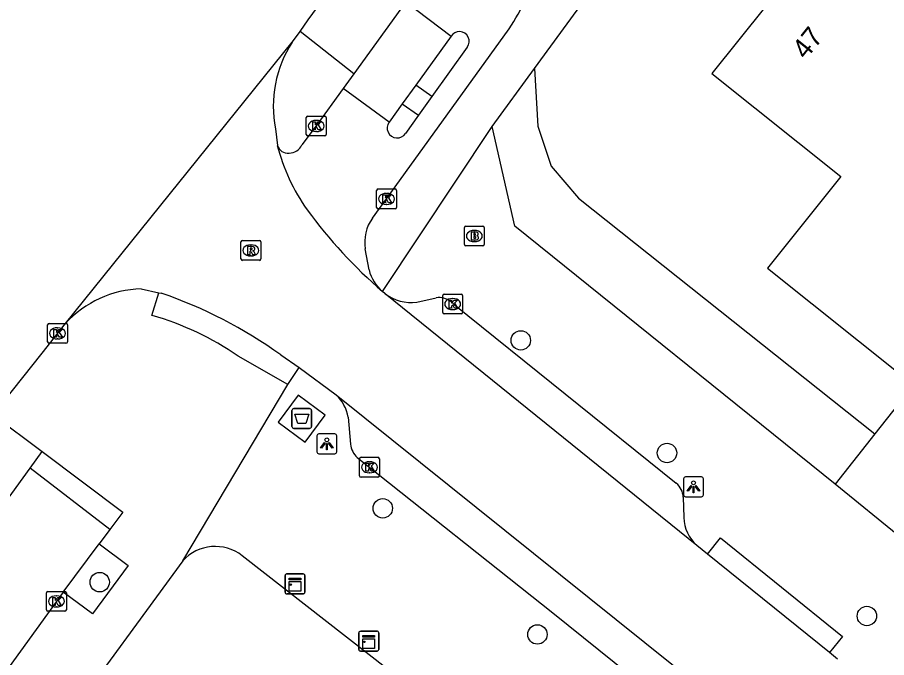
# Model space of a CAD drawing. Extents: x 160107 to 160928, y 382056 to 382918.
# Drawn here: x 160421.79 to 160465.57, y 382582.18 to 382614.43 of the extents above; entities that cross this region are included whole.
import ezdxf

# ---------------------------------------------------------------- set-up
doc = ezdxf.new("R2010")
doc.units = 0
for name, color, linetype in [('IMGEO_Afval_apart_plaats', 7, 'Continuous'), ('IMGEO_Boom', 7, 'Continuous'), ('IMGEO_Brandkraan', 7, 'Continuous'), ('IMGEO_Groenvoorziening', 7, 'Continuous'), ('IMGEO_Kast', 7, 'Continuous'), ('IMGEO_Kolk', 7, 'Continuous'), ('IMGEO_Lichtpunt', 7, 'Continuous'), ('IMGEO_Pand', 7, 'Continuous'), ('IMGEO_Pand_nummerreeks', 7, 'Continuous'), ('IMGEO_Rijbaan_lokaal_gesloten', 7, 'Continuous'), ('IMGEO_Rijbaan_lokaal_open', 7, 'Continuous'), ('IMGEO_Rioolput', 7, 'Continuous'), ('IMGEO_Voetpad_gesloten', 7, 'Continuous'), ('IMGEO_Voetpad_open', 7, 'Continuous')]:
    doc.layers.add(name, color=color, linetype=linetype)

msp = doc.modelspace()

# ---------------------------------------------------------------- linework, layer by layer
at = {"layer": 'IMGEO_Afval_apart_plaats'}
for p, q in [((160435.613, 382593.824), (160435.613, 382594.624)), ((160435.613, 382594.624), (160435.613, 382593.824)), ((160435.713, 382594.724), (160436.503, 382594.724)), ((160436.503, 382594.724), (160435.713, 382594.724)), ((160436.603, 382594.624), (160436.603, 382593.824)), ((160436.603, 382593.824), (160436.603, 382594.624)), ((160436.503, 382593.724), (160435.713, 382593.724)), ((160435.713, 382593.724), (160436.503, 382593.724))]:
    msp.add_line(p, q, dxfattribs=at)
msp.add_lwpolyline([(160435.756, 382594.438), (160436.46, 382594.438), (160436.311, 382593.968), (160435.905, 382593.968), (160435.756, 382594.438)], dxfattribs=at)
for centre, start, end in [((160435.713, 382594.624), 90, 180), ((160435.713, 382594.624), 90, 180), ((160436.503, 382594.624), 0, 90), ((160436.503, 382594.624), 360, 90), ((160435.713, 382593.824), 180, 270), ((160435.713, 382593.824), 180, 270), ((160436.503, 382593.824), 270, 0), ((160436.503, 382593.824), 270, 0)]:
    msp.add_arc(centre, 0.1, start, end, dxfattribs=at)
at = {"layer": 'IMGEO_Boom'}
for centre in [(160447.142, 382598.162), (160454.506, 382592.489), (160440.191, 382589.702), (160425.936, 382585.981), (160464.571, 382584.275), (160447.979, 382583.347)]:
    msp.add_circle(centre, 0.489, dxfattribs=at)
at = {"layer": 'IMGEO_Brandkraan'}
for p, q in [((160444.302, 382602.995), (160444.302, 382603.847)), ((160444.377, 382603.921), (160445.229, 382603.921)), ((160444.79, 382603.701), (160444.815, 382603.701)), ((160445.303, 382603.847), (160445.303, 382602.995)), ((160445.229, 382602.921), (160444.377, 382602.921)), ((160444.813, 382603.141), (160444.788, 382603.141))]:
    msp.add_line(p, q, dxfattribs=at)
for points in [[(160444.302, 382602.995), (160444.302, 382603.847)], [(160444.377, 382603.921), (160445.229, 382603.921)], [(160444.65, 382603.621), (160444.65, 382603.221), (160444.863, 382603.221)], [(160444.881, 382603.621), (160444.65, 382603.621)], [(160445.303, 382603.847), (160445.303, 382602.995)], [(160444.829, 382603.54), (160444.775, 382603.54), (160444.775, 382603.464)], [(160444.775, 382603.464), (160444.828, 382603.464)], [(160444.837, 382603.388), (160444.775, 382603.388), (160444.775, 382603.307)], [(160444.775, 382603.307), (160444.837, 382603.307)], [(160445.229, 382602.921), (160444.377, 382602.921)]]:
    msp.add_lwpolyline(points, dxfattribs=at)
for centre, radius, start, end in [((160444.379, 382603.845), 0.0765, 91.552, 178.448), ((160444.379, 382603.845), 0.0765, 91.552, 178.448), ((160444.885, 382603.476), 0.145, 59.4692, 91.5367), ((160444.91, 382603.523), 0.0922, 285.5137, 58.1501), ((160445.227, 382603.845), 0.0765, 1.552, 88.448), ((160445.227, 382603.845), 0.0765, 1.552, 88.448), ((160444.83, 382603.502), 0.0379, 267.8285, 90.9355), ((160444.838, 382603.347), 0.0404, 269.8759, 90.5077), ((160444.869, 382603.472), 0.251, 268.6676, 293.5347), ((160444.915, 382603.331), 0.105, 301.3115, 78.989), ((160444.379, 382602.997), 0.0765, 181.552, 268.448), ((160444.379, 382602.997), 0.0765, 181.552, 268.448), ((160445.227, 382602.997), 0.0765, 271.552, 358.448), ((160445.227, 382602.997), 0.0765, 271.552, 358.448)]:
    msp.add_arc(centre, radius, start, end, dxfattribs=at)
for centre, major_axis, ratio, start_param, end_param in [((160444.789, 382603.421), (-0.387, 0.002), 0.722429, 4.712389, 7.853982), ((160444.814, 382603.421), (-0.39, 0.002), 0.717154, 1.570796, 4.712389)]:
    msp.add_ellipse(centre, major_axis=major_axis, ratio=ratio, start_param=start_param, end_param=end_param, dxfattribs=at)
at = {"layer": 'IMGEO_Groenvoorziening'}
msp.add_lwpolyline([(160447.829, 382611.851), (160448.003, 382608.946), (160448.669, 382606.931), (160450.051, 382605.319), (160464.977, 382593.454)], dxfattribs=at)
at = {"layer": 'IMGEO_Kast'}
for p, q in [((160435.274, 382585.47), (160435.274, 382586.311)), ((160435.274, 382586.311), (160435.274, 382585.47)), ((160435.349, 382586.395), (160436.19, 382586.395)), ((160436.19, 382586.395), (160435.349, 382586.395)), ((160436.274, 382586.32), (160436.274, 382585.479)), ((160436.274, 382585.479), (160436.274, 382586.32)), ((160436.199, 382585.395), (160435.358, 382585.395)), ((160435.358, 382585.395), (160436.199, 382585.395)), ((160439.061, 382583.509), (160439.902, 382583.509)), ((160439.902, 382583.509), (160439.061, 382583.509)), ((160438.986, 382582.584), (160438.986, 382583.425)), ((160438.986, 382583.425), (160438.986, 382582.584)), ((160439.986, 382583.434), (160439.986, 382582.593)), ((160439.986, 382582.593), (160439.986, 382583.434)), ((160439.911, 382582.509), (160439.07, 382582.509)), ((160439.07, 382582.509), (160439.911, 382582.509))]:
    msp.add_line(p, q, dxfattribs=at)
for points in [[(160435.469, 382586.185), (160436.069, 382586.185), (160436.069, 382586.1), (160435.469, 382586.1), (160435.469, 382586.185)], [(160435.469, 382586.01), (160436.069, 382586.01), (160436.069, 382585.521), (160435.469, 382585.521), (160435.469, 382586.01)], [(160439.181, 382583.299), (160439.781, 382583.299), (160439.781, 382583.214), (160439.181, 382583.214), (160439.181, 382583.299)], [(160439.181, 382583.124), (160439.781, 382583.124), (160439.781, 382582.635), (160439.181, 382582.635), (160439.181, 382583.124)]]:
    msp.add_lwpolyline(points, dxfattribs=at)
for centre in [(160435.553, 382585.859), (160439.265, 382582.973)]:
    msp.add_circle(centre, 0.0377, dxfattribs=at)
for centre, start, end in [((160435.352, 382586.317), 92.4484, 184.2845), ((160435.352, 382586.317), 92.4484, 184.2845), ((160436.196, 382586.317), 2.4484, 94.2845), ((160436.196, 382586.317), 2.4484, 94.2845), ((160435.352, 382585.473), 182.4484, 274.2845), ((160435.352, 382585.473), 182.4484, 274.2845), ((160436.196, 382585.473), 272.4484, 4.2845), ((160436.196, 382585.473), 272.4484, 4.2845), ((160439.064, 382583.431), 92.4484, 184.2845), ((160439.064, 382583.431), 92.4484, 184.2845), ((160439.908, 382583.431), 2.4484, 94.2845), ((160439.908, 382583.431), 2.4484, 94.2845), ((160439.064, 382582.587), 182.4484, 274.2845), ((160439.064, 382582.587), 182.4484, 274.2845), ((160439.908, 382582.587), 272.4484, 4.2845), ((160439.908, 382582.587), 272.4484, 4.2845)]:
    msp.add_arc(centre, 0.0779, start, end, dxfattribs=at)
at = {"layer": 'IMGEO_Kolk'}
for p, q in [((160436.34, 382608.538), (160436.34, 382609.39)), ((160436.415, 382609.464), (160437.267, 382609.464)), ((160437.341, 382609.39), (160437.341, 382608.538)), ((160436.828, 382609.244), (160436.853, 382609.244)), ((160437.267, 382608.464), (160436.415, 382608.464)), ((160436.851, 382608.684), (160436.826, 382608.684)), ((160439.955, 382605.789), (160440.807, 382605.789)), ((160439.88, 382604.863), (160439.88, 382605.715)), ((160440.368, 382605.569), (160440.393, 382605.569)), ((160440.881, 382605.715), (160440.881, 382604.863)), ((160440.391, 382605.009), (160440.366, 382605.009)), ((160440.807, 382604.789), (160439.955, 382604.789)), ((160443.21, 382599.566), (160443.21, 382600.418)), ((160443.285, 382600.492), (160444.137, 382600.492)), ((160443.698, 382600.272), (160443.723, 382600.272)), ((160444.211, 382600.418), (160444.211, 382599.566)), ((160443.721, 382599.712), (160443.696, 382599.712)), ((160444.137, 382599.492), (160443.285, 382599.492)), ((160423.31, 382598.09), (160423.31, 382598.942)), ((160423.385, 382599.016), (160424.237, 382599.016)), ((160423.798, 382598.796), (160423.823, 382598.796)), ((160424.311, 382598.942), (160424.311, 382598.09)), ((160424.237, 382598.016), (160423.385, 382598.016)), ((160423.821, 382598.236), (160423.796, 382598.236)), ((160439.095, 382592.271), (160439.947, 382592.271)), ((160439.02, 382591.345), (160439.02, 382592.197)), ((160439.508, 382592.051), (160439.533, 382592.051)), ((160440.021, 382592.197), (160440.021, 382591.345)), ((160439.531, 382591.491), (160439.506, 382591.491)), ((160439.947, 382591.271), (160439.095, 382591.271)), ((160423.254, 382584.587), (160423.254, 382585.439)), ((160423.329, 382585.513), (160424.181, 382585.513)), ((160423.742, 382585.293), (160423.767, 382585.293)), ((160424.255, 382585.439), (160424.255, 382584.587)), ((160424.181, 382584.513), (160423.329, 382584.513)), ((160423.765, 382584.733), (160423.74, 382584.733))]:
    msp.add_line(p, q, dxfattribs=at)
for points in [[(160436.34, 382608.538), (160436.34, 382609.39)], [(160436.415, 382609.464), (160437.267, 382609.464)], [(160437.341, 382609.39), (160437.341, 382608.538)], [(160436.661, 382609.164), (160436.784, 382609.164), (160436.784, 382609.013), (160436.914, 382609.164), (160437.078, 382609.164), (160436.932, 382609.013), (160437.085, 382608.764), (160436.933, 382608.764), (160436.848, 382608.928), (160436.784, 382608.861), (160436.784, 382608.764), (160436.661, 382608.764), (160436.661, 382609.164)], [(160437.267, 382608.464), (160436.415, 382608.464)], [(160439.955, 382605.789), (160440.807, 382605.789)], [(160439.88, 382604.863), (160439.88, 382605.715)], [(160440.201, 382605.489), (160440.324, 382605.489), (160440.324, 382605.338), (160440.454, 382605.489), (160440.618, 382605.489), (160440.472, 382605.338), (160440.625, 382605.089), (160440.473, 382605.089), (160440.388, 382605.253), (160440.324, 382605.186), (160440.324, 382605.089), (160440.201, 382605.089), (160440.201, 382605.489)], [(160440.881, 382605.715), (160440.881, 382604.863)], [(160440.807, 382604.789), (160439.955, 382604.789)], [(160443.21, 382599.566), (160443.21, 382600.418)], [(160443.285, 382600.492), (160444.137, 382600.492)], [(160443.531, 382600.192), (160443.654, 382600.192), (160443.654, 382600.041), (160443.784, 382600.192), (160443.948, 382600.192), (160443.802, 382600.041), (160443.955, 382599.792), (160443.803, 382599.792), (160443.718, 382599.956), (160443.654, 382599.889), (160443.654, 382599.792), (160443.531, 382599.792), (160443.531, 382600.192)], [(160444.211, 382600.418), (160444.211, 382599.566)], [(160444.137, 382599.492), (160443.285, 382599.492)], [(160423.31, 382598.09), (160423.31, 382598.942)], [(160423.385, 382599.016), (160424.237, 382599.016)], [(160424.311, 382598.942), (160424.311, 382598.09)], [(160423.631, 382598.716), (160423.754, 382598.716), (160423.754, 382598.565), (160423.884, 382598.716), (160424.048, 382598.716), (160423.902, 382598.565), (160424.055, 382598.316), (160423.903, 382598.316), (160423.818, 382598.48), (160423.754, 382598.413), (160423.754, 382598.316), (160423.631, 382598.316), (160423.631, 382598.716)], [(160424.237, 382598.016), (160423.385, 382598.016)], [(160439.095, 382592.271), (160439.947, 382592.271)], [(160439.02, 382591.345), (160439.02, 382592.197)], [(160439.341, 382591.971), (160439.464, 382591.971), (160439.464, 382591.82), (160439.594, 382591.971), (160439.758, 382591.971), (160439.612, 382591.82), (160439.765, 382591.571), (160439.613, 382591.571), (160439.528, 382591.735), (160439.464, 382591.668), (160439.464, 382591.571), (160439.341, 382591.571), (160439.341, 382591.971)], [(160440.021, 382592.197), (160440.021, 382591.345)], [(160439.947, 382591.271), (160439.095, 382591.271)], [(160423.254, 382584.587), (160423.254, 382585.439)], [(160423.329, 382585.513), (160424.181, 382585.513)], [(160423.575, 382585.213), (160423.698, 382585.213), (160423.698, 382585.062), (160423.828, 382585.213), (160423.992, 382585.213), (160423.846, 382585.062), (160423.999, 382584.813), (160423.847, 382584.813), (160423.762, 382584.977), (160423.698, 382584.91), (160423.698, 382584.813), (160423.575, 382584.813), (160423.575, 382585.213)], [(160424.255, 382585.439), (160424.255, 382584.587)], [(160424.181, 382584.513), (160423.329, 382584.513)]]:
    msp.add_lwpolyline(points, dxfattribs=at)
for centre, start, end in [((160436.417, 382609.388), 91.552, 178.448), ((160436.417, 382609.388), 91.552, 178.448), ((160437.265, 382609.388), 1.552, 88.448), ((160437.265, 382609.388), 1.552, 88.448), ((160436.417, 382608.54), 181.552, 268.448), ((160436.417, 382608.54), 181.552, 268.448), ((160437.265, 382608.54), 271.552, 358.448), ((160437.265, 382608.54), 271.552, 358.448), ((160439.957, 382605.713), 91.552, 178.448), ((160439.957, 382605.713), 91.552, 178.448), ((160440.805, 382605.713), 1.552, 88.448), ((160440.805, 382605.713), 1.552, 88.448), ((160439.957, 382604.865), 181.552, 268.448), ((160439.957, 382604.865), 181.552, 268.448), ((160440.805, 382604.865), 271.552, 358.448), ((160440.805, 382604.865), 271.552, 358.448), ((160443.287, 382600.416), 91.552, 178.448), ((160443.287, 382600.416), 91.552, 178.448), ((160444.135, 382600.416), 1.552, 88.448), ((160444.135, 382600.416), 1.552, 88.448), ((160443.287, 382599.568), 181.552, 268.448), ((160443.287, 382599.568), 181.552, 268.448), ((160444.135, 382599.568), 271.552, 358.448), ((160444.135, 382599.568), 271.552, 358.448), ((160423.387, 382598.94), 91.552, 178.448), ((160423.387, 382598.94), 91.552, 178.448), ((160424.235, 382598.94), 1.552, 88.448), ((160424.235, 382598.94), 1.552, 88.448), ((160423.387, 382598.092), 181.552, 268.448), ((160423.387, 382598.092), 181.552, 268.448), ((160424.235, 382598.092), 271.552, 358.448), ((160424.235, 382598.092), 271.552, 358.448), ((160439.097, 382592.195), 91.552, 178.448), ((160439.097, 382592.195), 91.552, 178.448), ((160439.945, 382592.195), 1.552, 88.448), ((160439.945, 382592.195), 1.552, 88.448), ((160439.097, 382591.347), 181.552, 268.448), ((160439.097, 382591.347), 181.552, 268.448), ((160439.945, 382591.347), 271.552, 358.448), ((160439.945, 382591.347), 271.552, 358.448), ((160423.331, 382585.437), 91.552, 178.448), ((160423.331, 382585.437), 91.552, 178.448), ((160424.179, 382585.437), 1.552, 88.448), ((160424.179, 382585.437), 1.552, 88.448), ((160423.331, 382584.589), 181.552, 268.448), ((160423.331, 382584.589), 181.552, 268.448), ((160424.179, 382584.589), 271.552, 358.448), ((160424.179, 382584.589), 271.552, 358.448)]:
    msp.add_arc(centre, 0.0765, start, end, dxfattribs=at)
for centre, major_axis, ratio, start_param, end_param in [((160436.827, 382608.964), (-0.387, 0.002), 0.722429, 4.712389, 7.853982), ((160436.852, 382608.964), (-0.39, 0.002), 0.717154, 1.570796, 4.712389), ((160440.367, 382605.289), (-0.387, 0.002), 0.722429, 4.712389, 7.853982), ((160440.392, 382605.289), (-0.39, 0.002), 0.717154, 1.570796, 4.712389), ((160443.697, 382599.992), (-0.387, 0.002), 0.722429, 4.712389, 7.853982), ((160443.722, 382599.992), (-0.39, 0.002), 0.717154, 1.570796, 4.712389), ((160423.797, 382598.516), (-0.387, 0.002), 0.722429, 4.712389, 7.853982), ((160423.822, 382598.516), (-0.39, 0.002), 0.717154, 1.570796, 4.712389), ((160439.507, 382591.771), (-0.387, 0.002), 0.722429, 4.712389, 7.853982), ((160439.532, 382591.771), (-0.39, 0.002), 0.717154, 1.570796, 4.712389), ((160423.741, 382585.013), (-0.387, 0.002), 0.722429, 4.712389, 7.853982), ((160423.766, 382585.013), (-0.39, 0.002), 0.717154, 1.570796, 4.712389)]:
    msp.add_ellipse(centre, major_axis=major_axis, ratio=ratio, start_param=start_param, end_param=end_param, dxfattribs=at)
at = {"layer": 'IMGEO_Lichtpunt'}
for p, q in [((160436.875, 382593.352), (160436.875, 382592.545)), ((160436.875, 382593.352), (160436.875, 382592.545)), ((160437.777, 382593.447), (160436.969, 382593.447)), ((160437.777, 382593.447), (160436.969, 382593.447)), ((160437.871, 382592.545), (160437.871, 382593.352)), ((160437.871, 382592.545), (160437.871, 382593.352)), ((160436.969, 382592.451), (160437.777, 382592.451)), ((160436.969, 382592.451), (160437.777, 382592.451)), ((160455.34, 382591.188), (160455.34, 382590.381)), ((160455.34, 382591.188), (160455.34, 382590.381)), ((160456.242, 382591.283), (160455.434, 382591.283)), ((160456.242, 382591.283), (160455.434, 382591.283)), ((160456.336, 382590.381), (160456.336, 382591.188)), ((160456.336, 382590.381), (160456.336, 382591.188)), ((160455.434, 382590.287), (160456.242, 382590.287)), ((160455.434, 382590.287), (160456.242, 382590.287))]:
    msp.add_line(p, q, dxfattribs=at)
for points in [[(160437.249, 382593.016), (160437.288, 382592.988), (160437.1, 382592.726), (160437.062, 382592.753), (160437.249, 382593.016)], [(160437.351, 382592.968), (160437.398, 382592.968), (160437.398, 382592.646), (160437.351, 382592.646), (160437.351, 382592.968)], [(160437.461, 382592.988), (160437.499, 382593.015), (160437.686, 382592.753), (160437.647, 382592.725), (160437.461, 382592.988)], [(160455.714, 382590.852), (160455.753, 382590.824), (160455.565, 382590.562), (160455.527, 382590.589), (160455.714, 382590.852)], [(160455.816, 382590.804), (160455.863, 382590.804), (160455.863, 382590.482), (160455.816, 382590.482), (160455.816, 382590.804)], [(160455.926, 382590.824), (160455.964, 382590.851), (160456.151, 382590.589), (160456.112, 382590.561), (160455.926, 382590.824)]]:
    msp.add_lwpolyline(points, dxfattribs=at)
for centre in [(160437.374, 382593.15), (160455.839, 382590.986)]:
    msp.add_circle(centre, 0.0994, dxfattribs=at)
for centre, start, end in [((160436.969, 382593.352), 90, 180), ((160436.969, 382593.352), 90, 180), ((160437.777, 382593.352), 0, 90), ((160437.777, 382593.352), 0, 90), ((160436.969, 382592.545), 180, 270), ((160436.969, 382592.545), 180, 270), ((160437.777, 382592.545), 270, 0), ((160437.777, 382592.545), 270, 360), ((160455.434, 382591.188), 90, 180), ((160455.434, 382591.188), 90, 180), ((160456.242, 382591.188), 0, 90), ((160456.242, 382591.188), 0, 90), ((160455.434, 382590.381), 180, 270), ((160455.434, 382590.381), 180, 270), ((160456.242, 382590.381), 270, 0), ((160456.242, 382590.381), 270, 360)]:
    msp.add_arc(centre, 0.0946, start, end, dxfattribs=at)
at = {"layer": 'IMGEO_Pand'}
msp.add_lwpolyline([(160475.509, 382618.245), (160472.259, 382622.139), (160472.107, 382621.949), (160466.446, 382614.871), (160462.136, 382618.318), (160456.77, 382611.608), (160463.264, 382606.415), (160459.571, 382601.796), (160466.396, 382596.337), (160471.313, 382602.486), (160467.185, 382606.098), (160474.119, 382614.769), (160475.347, 382614.015), (160477.432, 382615.94)], dxfattribs=at)
at = {"layer": 'IMGEO_Rijbaan_lokaal_gesloten'}
for points in [[(160436.025, 382613.729), (160436.428, 382614.314), (160437.427, 382615.674), (160438.434, 382616.761)], [(160435.632, 382613.186), (160435.89, 382613.533), (160436.025, 382613.729)], [(160424.212, 382599.014), (160435.632, 382613.186)], [(160420.558, 382594.413), (160423.042, 382597.522), (160424.212, 382599.014)]]:
    msp.add_lwpolyline(points, dxfattribs=at)
at = {"layer": 'IMGEO_Rijbaan_lokaal_open'}
for points in [[(160525.477, 382626.898), (160516.443, 382636.034), (160510.687, 382632.435), (160500, 382625.753), (160480.01, 382613.255), (160480.277, 382612.822), (160464.977, 382593.454)], [(160441.354, 382615.212), (160443.631, 382613.481)], [(160441.104, 382614.866), (160438.732, 382611.585)], [(160439.667, 382604.311), (160440.376, 382605.29), (160446.562, 382613.866)], [(160443.631, 382613.481), (160441.854, 382611.023)], [(160444.442, 382612.935), (160442.662, 382610.445)], [(160438.732, 382611.585), (160438.202, 382610.852)], [(160438.202, 382610.852), (160436.838, 382608.964), (160436.118, 382608.006)], [(160440.505, 382609.157), (160438.202, 382610.852)], [(160441.854, 382611.023), (160441.175, 382610.083)], [(160442.662, 382610.445), (160441.988, 382609.502)], [(160441.175, 382610.083), (160440.505, 382609.157)], [(160441.988, 382609.502), (160441.333, 382608.586)], [(160434.791, 382608.815), (160434.881, 382607.985)], [(160439.498, 382601.708), (160439.308, 382602.777)], [(160428.021, 382600.754), (160428.919, 382600.565)], [(160428.919, 382600.565), (160429.026, 382600.543)], [(160440.316, 382600.508), (160440.177, 382600.621)], [(160456.007, 382587.831), (160440.316, 382600.508)], [(160435.049, 382597.428), (160435.985, 382596.798)], [(160435.985, 382596.798), (160437.847, 382595.414)], [(160437.847, 382595.414), (160450.577, 382585.198), (160483.799, 382558.523)], [(160464.977, 382593.454), (160462.972, 382590.915)], [(160422.43, 382591.723), (160423.04, 382592.568)], [(160423.04, 382592.568), (160427.101, 382589.515), (160426.45, 382588.641)], [(160415.332, 382581.933), (160422.43, 382591.723)], [(160426.45, 382588.641), (160422.43, 382591.723)], [(160466.307, 382588.202), (160462.972, 382590.915)], [(160426.45, 382588.641), (160425.903, 382587.906)], [(160424.094, 382585.479), (160425.903, 382587.906)], [(160456.544, 382587.398), (160456.007, 382587.831)], [(160462.683, 382582.44), (160456.544, 382587.398)], [(160424.094, 382585.479), (160418.415, 382577.656)], [(160463.099, 382582.104), (160462.683, 382582.44)]]:
    msp.add_lwpolyline(points, dxfattribs=at)
for centre, radius, start, end in [((160436.728, 382620.328), 11.768, 326.6897, 343.1987), ((160444.052, 382613.231), 0.49, 322.8436, 149.2561), ((160440.571, 382609.969), 5.894, 146.9227, 191.2956), ((160440.913, 382608.863), 0.503, 144.2679, 326.5508), ((160435.41, 382608.149), 0.554, 197.2102, 276.8437), ((160444.244, 382610.353), 9.658, 194.192, 215.5262), ((160435.469, 382608.32), 0.721, 270.5539, 334.1919), ((160456.62, 382619.565), 25.084, 216.2246, 229.0426), ((160441.327, 382603.114), 2.047, 144.1915, 189.4649), ((160441.63, 382602.284), 2.208, 195.1211, 228.8612), ((160428.151, 382595.43), 5.325, 91.3982, 137.7049), ((160421.506, 382578.622), 23.175, 54.2404, 71.0651)]:
    msp.add_arc(centre, radius, start, end, dxfattribs=at)
at = {"layer": 'IMGEO_Rioolput'}
for p, q in [((160433.123, 382603.195), (160433.975, 382603.195)), ((160433.048, 382602.269), (160433.048, 382603.121)), ((160433.536, 382602.975), (160433.561, 382602.975)), ((160434.049, 382603.121), (160434.049, 382602.269)), ((160433.559, 382602.415), (160433.534, 382602.415)), ((160433.975, 382602.195), (160433.123, 382602.195))]:
    msp.add_line(p, q, dxfattribs=at)
for points in [[(160433.123, 382603.195), (160433.975, 382603.195)], [(160433.048, 382602.269), (160433.048, 382603.121)], [(160433.637, 382602.893), (160433.385, 382602.895), (160433.385, 382602.495)], [(160433.563, 382602.814), (160433.509, 382602.814), (160433.509, 382602.733)], [(160433.509, 382602.733), (160433.561, 382602.733)], [(160434.049, 382603.121), (160434.049, 382602.269)], [(160433.385, 382602.495), (160433.509, 382602.495), (160433.509, 382602.657), (160433.52, 382602.657)], [(160433.567, 382602.628), (160433.638, 382602.495), (160433.778, 382602.495), (160433.713, 382602.621)], [(160433.975, 382602.195), (160433.123, 382602.195)]]:
    msp.add_lwpolyline(points, dxfattribs=at)
for centre, radius, start, end in [((160433.125, 382603.119), 0.0765, 91.552, 178.448), ((160433.125, 382603.119), 0.0765, 91.552, 178.448), ((160433.973, 382603.119), 0.0765, 1.552, 88.448), ((160433.973, 382603.119), 0.0765, 1.552, 88.448), ((160433.545, 382602.922), 0.19, 274.7715, 282.9687), ((160433.569, 382602.718), 0.0964, 77.0061, 93.1865), ((160433.583, 382602.775), 0.0378, 276.6634, 79.6772), ((160433.636, 382602.783), 0.109, 350.3612, 89.416), ((160433.634, 382602.783), 0.112, 277.5842, 350.9817), ((160433.519, 382602.604), 0.0533, 26.0293, 88.6989), ((160433.618, 382602.568), 0.108, 29.5134, 73.7905), ((160433.125, 382602.271), 0.0765, 181.552, 268.448), ((160433.125, 382602.271), 0.0765, 181.552, 268.448), ((160433.973, 382602.271), 0.0765, 271.552, 358.448), ((160433.973, 382602.271), 0.0765, 271.552, 358.448)]:
    msp.add_arc(centre, radius, start, end, dxfattribs=at)
for centre, major_axis, ratio, start_param, end_param in [((160433.535, 382602.695), (-0.387, 0.002), 0.722429, 4.712389, 7.853982), ((160433.56, 382602.695), (-0.39, 0.002), 0.717154, 1.570796, 4.712389)]:
    msp.add_ellipse(centre, major_axis=major_axis, ratio=ratio, start_param=start_param, end_param=end_param, dxfattribs=at)
at = {"layer": 'IMGEO_Voetpad_gesloten'}
msp.add_lwpolyline([(160437.293, 382594.399), (160435.926, 382595.409), (160434.922, 382594.05), (160436.289, 382593.04), (160437.293, 382594.399)], dxfattribs=at)
at = {"layer": 'IMGEO_Voetpad_open'}
for points in [[(160447.829, 382611.851), (160456.245, 382623.385)], [(160438.732, 382611.585), (160436.025, 382613.729)], [(160445.702, 382608.935), (160447.829, 382611.851)], [(160442.662, 382610.445), (160441.854, 382611.023)], [(160441.175, 382610.083), (160441.988, 382609.502)], [(160440.177, 382600.621), (160445.702, 382608.935)], [(160462.972, 382590.915), (160446.842, 382603.909), (160445.702, 382608.935)], [(160428.569, 382599.419), (160428.919, 382600.565)], [(160441.902, 382600.085), (160442.883, 382600.311)], [(160443.614, 382600.125), (160443.779, 382599.974), (160454.972, 382590.961)], [(160435.406, 382595.933), (160432.912, 382597.37)], [(160435.406, 382595.933), (160435.985, 382596.798)], [(160430.115, 382587.054), (160435.406, 382595.933)], [(160420.558, 382594.413), (160423.04, 382592.568)], [(160438.444, 382594.293), (160438.559, 382592.932)], [(160438.907, 382592.26), (160448.753, 382584.442), (160458.029, 382576.973), (160473.398, 382564.68), (160480.457, 382559.016)], [(160455.322, 382590.261), (160455.354, 382589.239)], [(160425.903, 382587.906), (160427.368, 382586.824), (160425.57, 382584.389), (160424.094, 382585.479)], [(160456.544, 382587.398), (160457.197, 382588.207), (160463.336, 382583.249), (160462.683, 382582.44)], [(160430.115, 382587.054), (160424.126, 382578.857)], [(160445.752, 382577.45), (160433.113, 382587.311)]]:
    msp.add_lwpolyline(points, dxfattribs=at)
for centre, radius, start, end in [((160441.643, 382602.298), 2.228, 233.4488, 276.6839), ((160443.004, 382599.256), 1.062, 54.9163, 96.5322), ((160424.555, 382585.283), 14.694, 55.3382, 74.1466), ((160436.495, 382593.975), 1.974, 9.2761, 46.7999), ((160439.713, 382593.103), 1.167, 188.4531, 226.3023), ((160454.392, 382590.234), 0.93, 1.6877, 51.4424), ((160457.289, 382589.281), 1.935, 181.2385, 228.5232), ((160431.753, 382585.564), 2.214, 52.0985, 137.7008)]:
    msp.add_arc(centre, radius, start, end, dxfattribs=at)

# ---------------------------------------------------------------- texts
at = {"layer": 'IMGEO_Pand_nummerreeks'}
msp.add_text('47', height=1, rotation=51.3506, dxfattribs=at).set_placement((160461.499, 382612.27))

doc.saveas('drawing.dxf')
